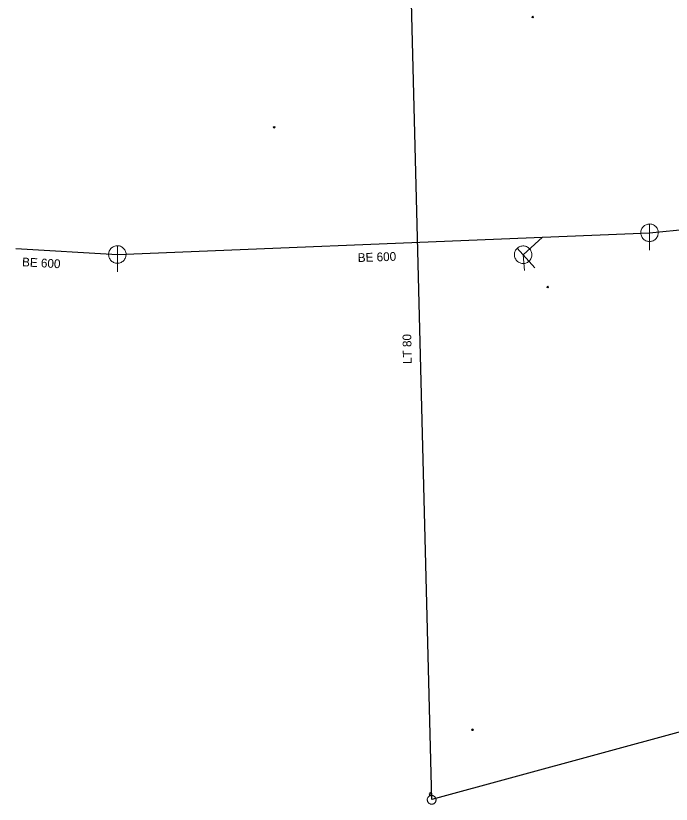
# Model space of a CAD drawing. Extents: x -783064 to -782702, y -1007904 to -1007145.
# Drawn here: x -783057 to -782982.2, y -1007831.4 to -1007741.4 of the extents above; entities that cross this region are included whole.
import ezdxf

# ---------------------------------------------------------------- set-up
doc = ezdxf.new("R2010")
doc.units = 0
doc.header["$LTSCALE"] = 0.4
doc.header["$PDMODE"] = 32
doc.header["$PDSIZE"] = 0.2
for name, color, linetype, lineweight in [('1', 7, 'Continuous', 13), ('11', 7, 'Continuous', 13), ('14', 7, 'Continuous', 13), ('17', 7, 'Continuous', 25), ('22', 7, 'Continuous', 13), ('23', 7, 'Continuous', 13)]:
    doc.layers.add(name, color=color, linetype=linetype, lineweight=lineweight)

msp = doc.modelspace()

# ---------------------------------------------------------------- linework, layer by layer
at = {"layer": '1'}
for p in [(-782997.989, -1007741.529), (-783027.51, -1007754.117), (-782996.277, -1007772.344), (-783004.859, -1007822.879)]:
    msp.add_point(p, dxfattribs=at)
at = {"layer": '11'}
for p, q in [((-782999.081, -1007768.659), (-782996.856, -1007766.648)), ((-782998.922, -1007770.458), (-782999.081, -1007768.659))]:
    msp.add_line(p, q, dxfattribs=at)
at = {"layer": '14', "lineweight": 25}
for p, q in [((-782984.649, -1007766.15), (-782937.159, -1007761.59)), ((-783057.019, -1007767.947), (-783045.42, -1007768.63))]:
    msp.add_line(p, q, dxfattribs=at)
msp.add_lwpolyline([(-783045.42, -1007768.63), (-782996.856, -1007766.648), (-782984.649, -1007766.15)], dxfattribs=at)
at = {"layer": '17'}
for points in [[(-783009.513, -1007830.854), (-783012.094, -1007729.406), (-783012.245, -1007726.341), (-783012.221, -1007724.861), (-783011.785, -1007708.13), (-783011.873, -1007699.631), (-783011.949, -1007690.495), (-783011.675, -1007674.297), (-783011.664, -1007660.033), (-783011.55, -1007647.2), (-783011.548, -1007646.713), (-783011.508, -1007646.299)], [(-782939.04, -1007808.423), (-782943.124, -1007812.766), (-783009.513, -1007830.854)]]:
    msp.add_lwpolyline(points, dxfattribs=at)
at = {"layer": '22'}
for p, q in [((-782984.649, -1007768.15), (-782984.648, -1007765.15)), ((-783045.42, -1007770.63), (-783045.419, -1007767.63)), ((-782997.739, -1007770.142), (-782999.751, -1007767.917))]:
    msp.add_line(p, q, dxfattribs=at)
for points in [[(-782983.649, -1007766.15), (-782983.654, -1007766.041), (-782983.672, -1007765.933), (-782983.702, -1007765.827), (-782983.742, -1007765.726), (-782983.794, -1007765.629), (-782983.856, -1007765.539), (-782983.928, -1007765.456), (-782984.008, -1007765.382), (-782984.096, -1007765.316), (-782984.19, -1007765.261), (-782984.29, -1007765.216), (-782984.395, -1007765.183), (-782984.502, -1007765.161), (-782984.611, -1007765.151), (-782984.721, -1007765.153), (-782984.829, -1007765.167), (-782984.936, -1007765.192), (-782985.039, -1007765.229), (-782985.137, -1007765.278), (-782985.229, -1007765.336), (-782985.315, -1007765.405), (-782985.392, -1007765.482), (-782985.461, -1007765.568), (-782985.52, -1007765.66), (-782985.568, -1007765.758), (-782985.605, -1007765.861), (-782985.631, -1007765.968), (-782985.645, -1007766.076), (-782985.648, -1007766.186), (-782985.638, -1007766.295), (-782985.617, -1007766.402), (-782985.583, -1007766.506), (-782985.539, -1007766.606), (-782985.484, -1007766.701), (-782985.418, -1007766.789), (-782985.344, -1007766.869), (-782985.261, -1007766.941), (-782985.171, -1007767.003), (-782985.075, -1007767.055), (-782984.973, -1007767.096), (-782984.868, -1007767.126), (-782984.76, -1007767.144), (-782984.65, -1007767.15), (-782984.541, -1007767.144), (-782984.433, -1007767.126), (-782984.328, -1007767.097), (-782984.226, -1007767.056), (-782984.129, -1007767.004), (-782984.039, -1007766.942), (-782983.956, -1007766.871), (-782983.881, -1007766.791), (-782983.816, -1007766.703), (-782983.76, -1007766.609), (-782983.716, -1007766.509), (-782983.682, -1007766.405), (-782983.66, -1007766.297), (-782983.65, -1007766.188)], [(-783044.42, -1007768.63), (-783044.425, -1007768.521), (-783044.443, -1007768.413), (-783044.473, -1007768.307), (-783044.513, -1007768.206), (-783044.565, -1007768.109), (-783044.627, -1007768.019), (-783044.699, -1007767.936), (-783044.779, -1007767.862), (-783044.867, -1007767.796), (-783044.961, -1007767.741), (-783045.061, -1007767.696), (-783045.166, -1007767.663), (-783045.273, -1007767.641), (-783045.382, -1007767.631), (-783045.492, -1007767.633), (-783045.6, -1007767.647), (-783045.707, -1007767.672), (-783045.81, -1007767.709), (-783045.908, -1007767.758), (-783046, -1007767.816), (-783046.086, -1007767.885), (-783046.163, -1007767.962), (-783046.232, -1007768.048), (-783046.291, -1007768.14), (-783046.339, -1007768.238), (-783046.376, -1007768.341), (-783046.402, -1007768.448), (-783046.416, -1007768.556), (-783046.419, -1007768.666), (-783046.409, -1007768.775), (-783046.388, -1007768.882), (-783046.354, -1007768.986), (-783046.31, -1007769.086), (-783046.255, -1007769.181), (-783046.189, -1007769.269), (-783046.115, -1007769.349), (-783046.032, -1007769.421), (-783045.942, -1007769.483), (-783045.846, -1007769.535), (-783045.744, -1007769.576), (-783045.639, -1007769.606), (-783045.531, -1007769.624), (-783045.421, -1007769.63), (-783045.312, -1007769.624), (-783045.204, -1007769.606), (-783045.099, -1007769.577), (-783044.997, -1007769.536), (-783044.9, -1007769.484), (-783044.81, -1007769.422), (-783044.727, -1007769.351), (-783044.652, -1007769.271), (-783044.587, -1007769.183), (-783044.531, -1007769.089), (-783044.487, -1007768.989), (-783044.453, -1007768.885), (-783044.431, -1007768.777), (-783044.421, -1007768.668)], [(-782998.338, -1007767.988), (-782998.416, -1007767.911), (-782998.502, -1007767.843), (-782998.595, -1007767.785), (-782998.693, -1007767.737), (-782998.796, -1007767.7), (-782998.902, -1007767.674), (-782999.012, -1007767.661), (-782999.121, -1007767.66), (-782999.23, -1007767.67), (-782999.337, -1007767.692), (-782999.441, -1007767.726), (-782999.541, -1007767.772), (-782999.635, -1007767.827), (-782999.723, -1007767.893), (-782999.803, -1007767.968), (-782999.874, -1007768.051), (-782999.936, -1007768.141), (-782999.988, -1007768.238), (-783000.028, -1007768.34), (-783000.057, -1007768.445), (-783000.075, -1007768.554), (-783000.08, -1007768.662), (-783000.074, -1007768.772), (-783000.056, -1007768.88), (-783000.025, -1007768.985), (-782999.984, -1007769.086), (-782999.931, -1007769.183), (-782999.869, -1007769.273), (-782999.797, -1007769.356), (-782999.716, -1007769.43), (-782999.629, -1007769.495), (-782999.534, -1007769.549), (-782999.434, -1007769.594), (-782999.33, -1007769.628), (-782999.222, -1007769.649), (-782999.113, -1007769.658), (-782999.004, -1007769.656), (-782998.895, -1007769.642), (-782998.789, -1007769.616), (-782998.686, -1007769.578), (-782998.588, -1007769.53), (-782998.496, -1007769.471), (-782998.41, -1007769.401), (-782998.333, -1007769.324), (-782998.265, -1007769.238), (-782998.207, -1007769.146), (-782998.159, -1007769.047), (-782998.122, -1007768.944), (-782998.097, -1007768.837), (-782998.083, -1007768.729), (-782998.081, -1007768.619), (-782998.091, -1007768.51), (-782998.113, -1007768.403), (-782998.147, -1007768.299), (-782998.192, -1007768.199), (-782998.248, -1007768.105), (-782998.314, -1007768.017)]]:
    msp.add_lwpolyline(points, close=True, dxfattribs=at)
at = {"layer": '23'}
msp.add_line((-783009.6, -1007830.206), (-783009.789, -1007830.258), dxfattribs=at)
for points in [[(-783009.048, -1007830.745), (-783009.065, -1007830.695), (-783009.087, -1007830.647), (-783009.114, -1007830.604), (-783009.145, -1007830.561), (-783009.181, -1007830.523), (-783009.221, -1007830.489), (-783009.264, -1007830.459), (-783009.309, -1007830.434), (-783009.357, -1007830.413), (-783009.407, -1007830.397), (-783009.458, -1007830.386), (-783009.511, -1007830.382), (-783009.563, -1007830.383), (-783009.614, -1007830.389), (-783009.665, -1007830.4), (-783009.716, -1007830.418), (-783009.762, -1007830.439), (-783009.808, -1007830.467), (-783009.849, -1007830.497), (-783009.888, -1007830.532), (-783009.922, -1007830.574), (-783009.952, -1007830.616), (-783009.978, -1007830.663), (-783009.999, -1007830.71), (-783010.014, -1007830.759), (-783010.023, -1007830.812), (-783010.028, -1007830.863), (-783010.027, -1007830.916), (-783010.02, -1007830.968), (-783010.01, -1007831.018), (-783009.993, -1007831.068), (-783009.971, -1007831.116), (-783009.944, -1007831.161), (-783009.913, -1007831.203), (-783009.877, -1007831.239), (-783009.837, -1007831.274), (-783009.795, -1007831.305), (-783009.748, -1007831.331), (-783009.7, -1007831.351)], [(-783009.808, -1007830.467), (-783009.849, -1007830.497), (-783009.888, -1007830.532), (-783009.922, -1007830.574), (-783009.952, -1007830.616), (-783009.978, -1007830.663), (-783009.999, -1007830.71), (-783010.014, -1007830.759), (-783010.023, -1007830.812), (-783010.028, -1007830.863), (-783010.027, -1007830.916), (-783010.02, -1007830.968), (-783010.01, -1007831.018), (-783009.993, -1007831.068), (-783009.971, -1007831.116), (-783009.944, -1007831.161), (-783009.913, -1007831.203), (-783009.877, -1007831.239), (-783009.837, -1007831.274), (-783009.795, -1007831.305), (-783009.748, -1007831.331), (-783009.7, -1007831.351), (-783009.652, -1007831.367), (-783009.599, -1007831.376), (-783009.548, -1007831.382), (-783009.495, -1007831.38), (-783009.443, -1007831.373), (-783009.393, -1007831.362), (-783009.343, -1007831.345), (-783009.295, -1007831.323), (-783009.25, -1007831.297), (-783009.209, -1007831.265), (-783009.17, -1007831.229), (-783009.136, -1007831.191), (-783009.106, -1007831.146), (-783009.08, -1007831.102), (-783009.06, -1007831.054), (-783009.044, -1007831.003), (-783009.034, -1007830.952), (-783009.029, -1007830.9)], [(-783009.7, -1007831.351), (-783009.652, -1007831.367), (-783009.599, -1007831.376), (-783009.548, -1007831.382), (-783009.495, -1007831.38), (-783009.443, -1007831.373), (-783009.393, -1007831.362), (-783009.343, -1007831.345), (-783009.295, -1007831.323), (-783009.25, -1007831.297), (-783009.209, -1007831.265), (-783009.17, -1007831.229), (-783009.136, -1007831.191), (-783009.106, -1007831.146), (-783009.08, -1007831.102), (-783009.06, -1007831.054), (-783009.044, -1007831.003), (-783009.034, -1007830.952), (-783009.029, -1007830.9), (-783009.031, -1007830.847), (-783009.037, -1007830.796), (-783009.048, -1007830.745), (-783009.065, -1007830.695), (-783009.087, -1007830.647), (-783009.114, -1007830.604), (-783009.145, -1007830.561), (-783009.181, -1007830.523), (-783009.221, -1007830.489), (-783009.264, -1007830.459), (-783009.309, -1007830.434), (-783009.357, -1007830.413), (-783009.407, -1007830.397), (-783009.458, -1007830.386), (-783009.511, -1007830.382), (-783009.563, -1007830.383), (-783009.614, -1007830.389), (-783009.665, -1007830.4), (-783009.716, -1007830.418), (-783009.762, -1007830.439), (-783009.808, -1007830.467)], [(-783009.763, -1007830.351), (-783009.803, -1007830.208), (-783009.747, -1007830.036), (-783009.613, -1007830.156), (-783009.574, -1007830.3)], [(-783009.029, -1007830.9), (-783009.031, -1007830.847), (-783009.037, -1007830.796), (-783009.048, -1007830.745)]]:
    msp.add_lwpolyline(points, dxfattribs=at)

# ---------------------------------------------------------------- texts
at = {"layer": '1'}
for s, rotation, p in [('BE 600', 2, (-783017.951, -1007769.495)), ('BE 600', 357, (-783056.32, -1007769.976)), ('LT 80 ', 91, (-783011.798, -1007781.122))]:
    msp.add_text(s, height=1, rotation=rotation, dxfattribs=at).set_placement(p)

doc.saveas('drawing.dxf')
